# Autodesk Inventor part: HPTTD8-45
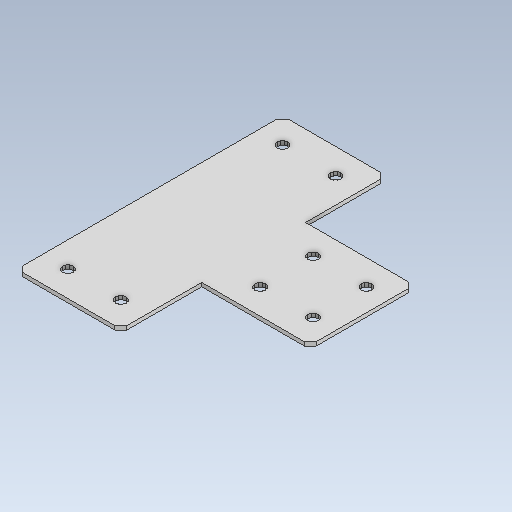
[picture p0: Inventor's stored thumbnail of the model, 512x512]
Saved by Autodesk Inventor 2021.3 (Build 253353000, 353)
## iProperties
Created: 2022-02
Part Number: HPTTD8-45
Material: 一般
Document SubType Name: Modeling
Designer: kengo
Density: 1 g/cm^3
Appearance: 既定
Author: kengo
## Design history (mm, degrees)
feature "HPTTD8-45"
node "ソリッド1"
